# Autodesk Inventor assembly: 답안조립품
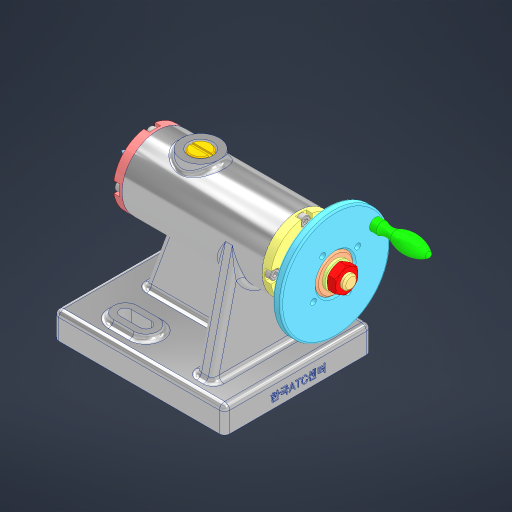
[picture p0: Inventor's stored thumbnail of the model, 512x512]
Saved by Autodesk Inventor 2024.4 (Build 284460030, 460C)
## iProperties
Created: 2026-09
Part Number: 답안조립품
Document SubType Name: Assembly
Designer: user
Author: user
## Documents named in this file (18)
- C:\Users\user\Desktop\760903V1007\답안조립품.iam
- D:\PM 06;50 [평일반] 김민준 [2026-07-14종강]\인벤터2급\2011-08-27 2급 기출문제\메인기어\핸들\핸들.ipt
- D:\PM 06;50 [평일반] 김민준 [2026-07-14종강]\인벤터2급\2011-08-27 2급 기출문제\메인기어\플랜지\플랜지.ipt
- D:\PM 06;50 [평일반] 김민준 [2026-07-14종강]\인벤터2급\2011-08-27 2급 기출문제\메인기어\평행 키 4x4x10\평행 키 4x4x10.ipt
- D:\PM 06;50 [평일반] 김민준 [2026-07-14종강]\인벤터2급\2011-08-27 2급 기출문제\메인기어\평 와셔 M8\평 와셔 M8.ipt
- D:\PM 06;50 [평일반] 김민준 [2026-07-14종강]\인벤터2급\2011-08-27 2급 기출문제\메인기어\커버\커버.ipt
- D:\PM 06;50 [평일반] 김민준 [2026-07-14종강]\인벤터2급\2011-08-27 2급 기출문제\메인기어\슬리브\슬리브.ipt
- D:\PM 06;50 [평일반] 김민준 [2026-07-14종강]\인벤터2급\2011-08-27 2급 기출문제\메인기어\스톱퍼\스톱퍼.ipt
- D:\PM 06;50 [평일반] 김민준 [2026-07-14종강]\인벤터2급\2011-08-27 2급 기출문제\메인기어\센터홀더\센터홀더.ipt
- D:\PM 06;50 [평일반] 김민준 [2026-07-14종강]\인벤터2급\2011-08-27 2급 기출문제\메인기어\센터\센터.ipt
- D:\PM 06;50 [평일반] 김민준 [2026-07-14종강]\인벤터2급\2011-08-27 2급 기출문제\메인기어\부시\부시.ipt
- D:\PM 06;50 [평일반] 김민준 [2026-07-14종강]\인벤터2급\2011-08-27 2급 기출문제\메인기어\멈춤나사 M3\멈춤나사 M3.ipt
- D:\PM 06;50 [평일반] 김민준 [2026-07-14종강]\인벤터2급\2011-08-27 2급 기출문제\메인기어\돌림판\돌림판.ipt
- D:\PM 06;50 [평일반] 김민준 [2026-07-14종강]\인벤터2급\2011-08-27 2급 기출문제\메인기어\나사축\나사축.ipt
- D:\PM 06;50 [평일반] 김민준 [2026-07-14종강]\인벤터2급\2011-08-27 2급 기출문제\메인기어\가이드 부시\가이드 부시.ipt
- D:\PM 06;50 [평일반] 김민준 [2026-07-14종강]\인벤터2급\2011-08-27 2급 기출문제\메인기어\6각 너트 M8\6각 너트 M8.ipt
- D:\PM 06;50 [평일반] 김민준 [2026-07-14종강]\인벤터2급\2011-08-27 2급 기출문제\메인기어\6각 구멍붙이 볼트 M3x8\6각 구멍붙이 볼트 M3x8.ipt
- C:\Users\user\Desktop\760903V1007\본체.ipt
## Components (12 placed, 5 different names)
1. 핸들:1
2. 플랜지:1
3. 가이드 부시:1 — 플러쉬:2, 플러쉬:3
4. 6각 너트 M8:1
5. 6각 구멍붙이 볼트 M3x8:1
6. 6각 구멍붙이 볼트 M3x8:2
7. 6각 구멍붙이 볼트 M3x8:3
8. 6각 구멍붙이 볼트 M3x8:4
9. 6각 구멍붙이 볼트 M3x8:5
10. 6각 구멍붙이 볼트 M3x8:6
11. 6각 구멍붙이 볼트 M3x8:7
12. 6각 구멍붙이 볼트 M3x8:8
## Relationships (2: Flush 2)
- 플러쉬:2 [Flush]: 가이드 부시:1
- 플러쉬:3 [Flush]: 가이드 부시:1
